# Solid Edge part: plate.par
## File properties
Author: Robert a Rhodes jr
Template: Normal.par
Last saved by: Cadcim
Revision: 5
Application: Solid Edge
Accuracy: 0.99
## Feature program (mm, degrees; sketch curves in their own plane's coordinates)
sketch for "unnamed Protrusion 1" plane through (0, 0, 0) normal (0, 0, 1) x-axis (1, 0, 0)
  circle centre (0, 0) radius 59.0444
extrude "unnamed Protrusion 1" add finite 19.05 along -normal
sketch for "Hole_1" plane through (0, 0, 0) normal (0, 0, 1) x-axis (0, 1, 0)
  hole centre (-28.483, 27.7745) bore radius 8
hole "Hole_1" diameter 16 through
sketch for "ExtrudedCutout_1" plane through (0, 0, 0) normal (0, 0, 1) x-axis (0, 1, 0)
  line (-59.0916, 45.0627) -> (-29.6658, 45.0627)
  arc centre (-29.6658, 29.4258) radius 15.6369 from (-29.6658, 45.0627) to (-14.0289, 29.4258) cw
  line (-14.0289, 29.4258) -> (-14.0289, 27.7745)
  arc centre (-28.483, 27.7745) radius 14.4541 from (-14.0289, 27.7745) to (-28.483, 13.3204) cw
  line (-28.483, 13.3204) -> (-59.0916, 13.3204)
  line (-59.0916, 13.3204) -> (-59.0916, 45.0627)
extrude "ExtrudedCutout_1" cut finite 6.35 along -normal
pattern "unnamed Pattern 1" of "Hole_1"
hole "unnamed Hole 1" through
hole "unnamed Hole 2" through
hole "unnamed Hole 3" through
mirror "unnamed Mirror 1" of "ExtrudedCutout_1" about plane through (0, 0, 0) normal (0, -1, 0)
extrude "unnamed Cutout 1" cut finite 6.35
mirror "unnamed Mirror 2" of "ExtrudedCutout_1" about plane through (0, 0, 0) normal (1, 0, 0)
extrude "unnamed Cutout 2" cut finite 6.35
mirror "unnamed Mirror 3" of "unnamed Mirror 1" about plane through (0, 0, 0) normal (1, 0, 0)
extrude "unnamed Cutout 3" cut finite 6.35
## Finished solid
Body 1: solid body, 31 faces, 81 edges, 48 vertices.
  Faces by surface: plane 18, cylinder 13
  Edges by curve: line 48, circle 33
Bounding box of the edges (mm): 118.089 x 118.089 x 19.050, from (-59.0444, -59.0444, -19.05) to (59.0444, 59.0444, 0).
Cylindrical faces by radius (mm): R8 x4, R14.4541 x4, R15.6369 x4, R59.0444 x1
Planar faces by outward normal: +x 4, +y 2, +z 5, -x 4, -y 2, -z 1
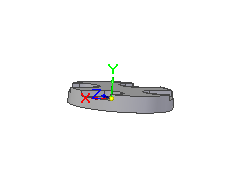
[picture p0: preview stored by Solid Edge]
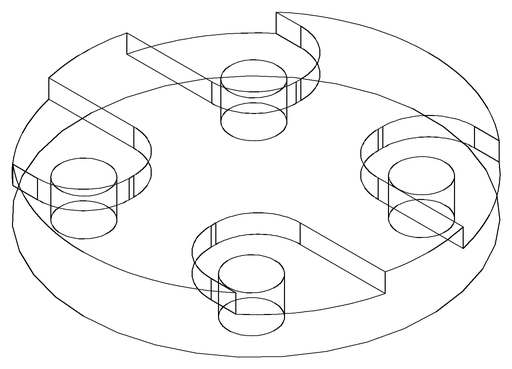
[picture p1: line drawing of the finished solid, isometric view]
